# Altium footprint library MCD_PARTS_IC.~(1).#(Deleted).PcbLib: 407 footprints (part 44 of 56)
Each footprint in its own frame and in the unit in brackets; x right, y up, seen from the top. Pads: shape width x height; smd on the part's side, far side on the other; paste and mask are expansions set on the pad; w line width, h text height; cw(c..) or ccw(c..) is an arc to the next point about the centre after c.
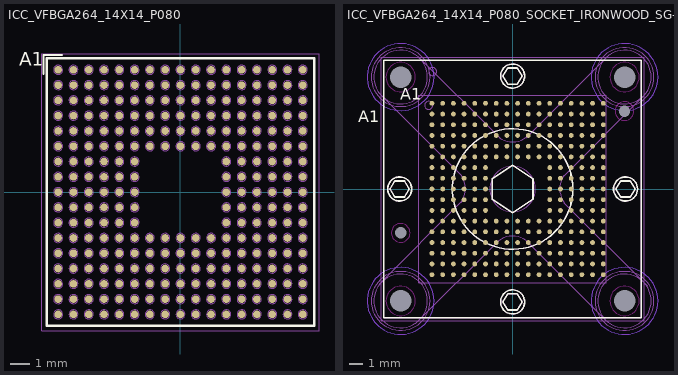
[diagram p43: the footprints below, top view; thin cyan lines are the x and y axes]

## ICC_VFBGA264_14X14_P080 [mm] "MCD-03176"
height 1
pads (264):
  round 0.4 smd mask+0.05: A1(-6.4,6.4) A2(-5.6,6.4) A3(-4.8,6.4) A4(-4,6.4) A5(-3.2,6.4) A6(-2.4,6.4) A7(-1.6,6.4) A8(-0.8,6.4) A9(0,6.4) A10(0.8,6.4) A11(1.6,6.4) A12(2.4,6.4) A13(3.2,6.4) A14(4,6.4) A15(4.8,6.4) A16(5.6,6.4) A17(6.4,6.4) B1(-6.4,5.6) B2(-5.6,5.6) B3(-4.8,5.6) B4(-4,5.6) B5(-3.2,5.6) B6(-2.4,5.6) B7(-1.6,5.6) B8(-0.8,5.6) B9(0,5.6) B10(0.8,5.6) B11(1.6,5.6) B12(2.4,5.6) B13(3.2,5.6) B14(4,5.6) B15(4.8,5.6) B16(5.6,5.6) B17(6.4,5.6) C1(-6.4,4.8) C2(-5.6,4.8) C3(-4.8,4.8) C4(-4,4.8) C5(-3.2,4.8) C6(-2.4,4.8) C7(-1.6,4.8) C8(-0.8,4.8) C9(0,4.8) C10(0.8,4.8) C11(1.6,4.8) C12(2.4,4.8) C13(3.2,4.8) C14(4,4.8) C15(4.8,4.8) C16(5.6,4.8) C17(6.4,4.8) D1(-6.4,4) D2(-5.6,4) D3(-4.8,4) D4(-4,4) D5(-3.2,4) D6(-2.4,4) D7(-1.6,4) D8(-0.8,4) D9(0,4) D10(0.8,4) D11(1.6,4) D12(2.4,4) D13(3.2,4) D14(4,4) D15(4.8,4) D16(5.6,4) D17(6.4,4) E1(-6.4,3.2) E2(-5.6,3.2) E3(-4.8,3.2) E4(-4,3.2) E5(-3.2,3.2) E6(-2.4,3.2) E7(-1.6,3.2) E8(-0.8,3.2) E9(0,3.2) E10(0.8,3.2) E11(1.6,3.2) E12(2.4,3.2) E13(3.2,3.2) E14(4,3.2) E15(4.8,3.2) E16(5.6,3.2) E17(6.4,3.2) F1(-6.4,2.4) F2(-5.6,2.4) F3(-4.8,2.4) F4(-4,2.4) F5(-3.2,2.4) F6(-2.4,2.4) F7(-1.6,2.4) F8(-0.8,2.4) F9(0,2.4) F10(0.8,2.4) F11(1.6,2.4) F12(2.4,2.4) F13(3.2,2.4) F14(4,2.4) F15(4.8,2.4) F16(5.6,2.4) F17(6.4,2.4) G1(-6.4,1.6) G2(-5.6,1.6) G3(-4.8,1.6) G4(-4,1.6) G5(-3.2,1.6) G6(-2.4,1.6) G12(2.4,1.6) G13(3.2,1.6) G14(4,1.6) G15(4.8,1.6) G16(5.6,1.6) G17(6.4,1.6) H1(-6.4,0.8) H2(-5.6,0.8) H3(-4.8,0.8) H4(-4,0.8) H5(-3.2,0.8) H6(-2.4,0.8) H12(2.4,0.8) H13(3.2,0.8) H14(4,0.8) H15(4.8,0.8) H16(5.6,0.8) H17(6.4,0.8) J1(-6.4,0) J2(-5.6,0) J3(-4.8,0) J4(-4,0) J5(-3.2,0) J6(-2.4,0) J12(2.4,0) J13(3.2,0) J14(4,0) J15(4.8,0) J16(5.6,0) J17(6.4,0) K1(-6.4,-0.8) K2(-5.6,-0.8) K3(-4.8,-0.8) K4(-4,-0.8) K5(-3.2,-0.8) K6(-2.4,-0.8) K12(2.4,-0.8) K13(3.2,-0.8) K14(4,-0.8) K15(4.8,-0.8) K16(5.6,-0.8) K17(6.4,-0.8) L1(-6.4,-1.6) L2(-5.6,-1.6) L3(-4.8,-1.6) L4(-4,-1.6) L5(-3.2,-1.6) L6(-2.4,-1.6) L12(2.4,-1.6) L13(3.2,-1.6) L14(4,-1.6) L15(4.8,-1.6) L16(5.6,-1.6) L17(6.4,-1.6) M1(-6.4,-2.4) M2(-5.6,-2.4) M3(-4.8,-2.4) M4(-4,-2.4) M5(-3.2,-2.4) M6(-2.4,-2.4) M7(-1.6,-2.4) M8(-0.8,-2.4) M9(0,-2.4) M10(0.8,-2.4) M11(1.6,-2.4) M12(2.4,-2.4) M13(3.2,-2.4) M14(4,-2.4) M15(4.8,-2.4) M16(5.6,-2.4) M17(6.4,-2.4) N1(-6.4,-3.2) N2(-5.6,-3.2) N3(-4.8,-3.2) N4(-4,-3.2) N5(-3.2,-3.2) N6(-2.4,-3.2) N7(-1.6,-3.2) N8(-0.8,-3.2) N9(0,-3.2) N10(0.8,-3.2) N11(1.6,-3.2) N12(2.4,-3.2) N13(3.2,-3.2) N14(4,-3.2) N15(4.8,-3.2) N16(5.6,-3.2) N17(6.4,-3.2) P1(-6.4,-4) P2(-5.6,-4) P3(-4.8,-4) P4(-4,-4) P5(-3.2,-4) P6(-2.4,-4) P7(-1.6,-4) P8(-0.8,-4) P9(0,-4) P10(0.8,-4) P11(1.6,-4) P12(2.4,-4) P13(3.2,-4) P14(4,-4) P15(4.8,-4) P16(5.6,-4) P17(6.4,-4) R1(-6.4,-4.8) R2(-5.6,-4.8) R3(-4.8,-4.8) R4(-4,-4.8) R5(-3.2,-4.8) R6(-2.4,-4.8) R7(-1.6,-4.8) R8(-0.8,-4.8) R9(0,-4.8) R10(0.8,-4.8) R11(1.6,-4.8) R12(2.4,-4.8) R13(3.2,-4.8) R14(4,-4.8) R15(4.8,-4.8) R16(5.6,-4.8) R17(6.4,-4.8) T1(-6.4,-5.6) T2(-5.6,-5.6) T3(-4.8,-5.6) T4(-4,-5.6) T5(-3.2,-5.6) T6(-2.4,-5.6) T7(-1.6,-5.6) T8(-0.8,-5.6) T9(0,-5.6) T10(0.8,-5.6) T11(1.6,-5.6) T12(2.4,-5.6) T13(3.2,-5.6) T14(4,-5.6) T15(4.8,-5.6) T16(5.6,-5.6) T17(6.4,-5.6) U1(-6.4,-6.4) U2(-5.6,-6.4) U3(-4.8,-6.4) U4(-4,-6.4) U5(-3.2,-6.4) U6(-2.4,-6.4) U7(-1.6,-6.4) U8(-0.8,-6.4) U9(0,-6.4) U10(0.8,-6.4) U11(1.6,-6.4) U12(2.4,-6.4) U13(3.2,-6.4) U14(4,-6.4) U15(4.8,-6.4) U16(5.6,-6.4) U17(6.4,-6.4)
Top Overlay:
  lines w0.12: -7.17,6.195 -7.17,7.17 -6.195,7.17 ; -7,-7 7,-7 7,7 -7,7 -7,-7
  text "A1" at -8.45,6.375 h1.2
M14-Top Assembly:
  drawing of 268 lines, arcs and shapes, not listed
  text "'.Designator'" at -2,-0.5 h0.75
  text "A1" at -6.8,6.175 h0.75
M16-Top Courtyard:
  lines w0.01: -7.25,-7.25 7.25,-7.25 7.25,7.25 -7.25,7.25 -7.25,-7.25
3D body: height 0.97, standoff 0.96, extent -6.249,5.776 -5.751,6.275
3D body: height 0.47, standoff -0.01, extent 2.96,-6.636 3.44,-6.164
3D body: height 0.47, standoff -0.01, extent 3.76,-6.636 4.24,-6.164
3D body: height 0.47, standoff -0.01, extent 4.56,-6.636 5.04,-6.164
3D body: height 0.47, standoff -0.01, extent 5.36,-6.636 5.84,-6.164
3D body: height 0.47, standoff -0.01, extent 6.16,-6.636 6.64,-6.164
3D body: height 0.47, standoff -0.01, extent -1.84,-6.636 -1.36,-6.164
3D body: height 0.47, standoff -0.01, extent -1.04,-6.636 -0.56,-6.164
3D body: height 0.47, standoff -0.01, extent -0.24,-6.636 0.24,-6.164
3D body: height 0.47, standoff -0.01, extent 0.56,-6.636 1.04,-6.164
3D body: height 0.47, standoff -0.01, extent 1.36,-6.636 1.84,-6.164
3D body: height 0.47, standoff -0.01, extent 2.16,-6.636 2.64,-6.164
3D body: height 0.47, standoff -0.01, extent -2.64,-6.636 -2.16,-6.164
3D body: height 0.47, standoff -0.01, extent -3.44,-6.636 -2.96,-6.164
3D body: height 0.47, standoff -0.01, extent -4.24,-6.636 -3.76,-6.164
3D body: height 0.47, standoff -0.01, extent -5.04,-6.636 -4.56,-6.164
3D body: height 0.47, standoff -0.01, extent -5.84,-6.636 -5.36,-6.164
3D body: height 0.47, standoff -0.01, extent -6.64,-6.636 -6.16,-6.164
3D body: height 0.47, standoff -0.01, extent 2.96,-5.836 3.44,-5.364
3D body: height 0.47, standoff -0.01, extent 3.76,-5.836 4.24,-5.364
3D body: height 0.47, standoff -0.01, extent 4.56,-5.836 5.04,-5.364
3D body: height 0.47, standoff -0.01, extent 5.36,-5.836 5.84,-5.364
3D body: height 0.47, standoff -0.01, extent 6.16,-5.836 6.64,-5.364
3D body: height 0.47, standoff -0.01, extent -1.84,-5.836 -1.36,-5.364
3D body: height 0.47, standoff -0.01, extent -1.04,-5.836 -0.56,-5.364
3D body: height 0.47, standoff -0.01, extent -0.24,-5.836 0.24,-5.364
3D body: height 0.47, standoff -0.01, extent 0.56,-5.836 1.04,-5.364
3D body: height 0.47, standoff -0.01, extent 1.36,-5.836 1.84,-5.364
3D body: height 0.47, standoff -0.01, extent 2.16,-5.836 2.64,-5.364
3D body: height 0.47, standoff -0.01, extent -2.64,-5.836 -2.16,-5.364
3D body: height 0.47, standoff -0.01, extent -3.44,-5.836 -2.96,-5.364
3D body: height 0.47, standoff -0.01, extent -4.24,-5.836 -3.76,-5.364
3D body: height 0.47, standoff -0.01, extent -5.04,-5.836 -4.56,-5.364
3D body: height 0.47, standoff -0.01, extent -5.84,-5.836 -5.36,-5.364
3D body: height 0.47, standoff -0.01, extent -6.64,-5.836 -6.16,-5.364
3D body: height 0.47, standoff -0.01, extent 2.96,-5.036 3.44,-4.564
3D body: height 0.47, standoff -0.01, extent 3.76,-5.036 4.24,-4.564
3D body: height 0.47, standoff -0.01, extent 4.56,-5.036 5.04,-4.564
3D body: height 0.47, standoff -0.01, extent 5.36,-5.036 5.84,-4.564
3D body: height 0.47, standoff -0.01, extent 6.16,-5.036 6.64,-4.564
3D body: height 0.47, standoff -0.01, extent -1.84,-5.036 -1.36,-4.564
3D body: height 0.47, standoff -0.01, extent -1.04,-5.036 -0.56,-4.564
3D body: height 0.47, standoff -0.01, extent -0.24,-5.036 0.24,-4.564
3D body: height 0.47, standoff -0.01, extent 0.56,-5.036 1.04,-4.564
3D body: height 0.47, standoff -0.01, extent 1.36,-5.036 1.84,-4.564
3D body: height 0.47, standoff -0.01, extent 2.16,-5.036 2.64,-4.564
3D body: height 0.47, standoff -0.01, extent -2.64,-5.036 -2.16,-4.564
3D body: height 0.47, standoff -0.01, extent -3.44,-5.036 -2.96,-4.564
3D body: height 0.47, standoff -0.01, extent -4.24,-5.036 -3.76,-4.564
3D body: height 0.47, standoff -0.01, extent -5.04,-5.036 -4.56,-4.564
3D body: height 0.47, standoff -0.01, extent -5.84,-5.036 -5.36,-4.564
3D body: height 0.47, standoff -0.01, extent -6.64,-5.036 -6.16,-4.564
3D body: height 0.47, standoff -0.01, extent 2.96,-4.236 3.44,-3.764
3D body: height 0.47, standoff -0.01, extent 3.76,-4.236 4.24,-3.764
3D body: height 0.47, standoff -0.01, extent 4.56,-4.236 5.04,-3.764
3D body: height 0.47, standoff -0.01, extent 5.36,-4.236 5.84,-3.764
3D body: height 0.47, standoff -0.01, extent 6.16,-4.236 6.64,-3.764
3D body: height 0.47, standoff -0.01, extent -1.84,-4.236 -1.36,-3.764
3D body: height 0.47, standoff -0.01, extent -1.04,-4.236 -0.56,-3.764
3D body: height 0.47, standoff -0.01, extent -0.24,-4.236 0.24,-3.764
3D body: height 0.47, standoff -0.01, extent 0.56,-4.236 1.04,-3.764
3D body: height 0.47, standoff -0.01, extent 1.36,-4.236 1.84,-3.764
3D body: height 0.47, standoff -0.01, extent 2.16,-4.236 2.64,-3.764
3D body: height 0.47, standoff -0.01, extent -2.64,-4.236 -2.16,-3.764
3D body: height 0.47, standoff -0.01, extent -3.44,-4.236 -2.96,-3.764
3D body: height 0.47, standoff -0.01, extent -4.24,-4.236 -3.76,-3.764
3D body: height 0.47, standoff -0.01, extent -5.04,-4.236 -4.56,-3.764
3D body: height 0.47, standoff -0.01, extent -5.84,-4.236 -5.36,-3.764
3D body: height 0.47, standoff -0.01, extent -6.64,-4.236 -6.16,-3.764
3D body: height 0.47, standoff -0.01, extent 2.96,-3.436 3.44,-2.964
3D body: height 0.47, standoff -0.01, extent 3.76,-3.436 4.24,-2.964
3D body: height 0.47, standoff -0.01, extent 4.56,-3.436 5.04,-2.964
3D body: height 0.47, standoff -0.01, extent 5.36,-3.436 5.84,-2.964
3D body: height 0.47, standoff -0.01, extent 6.16,-3.436 6.64,-2.964
3D body: height 0.47, standoff -0.01, extent -1.84,-3.436 -1.36,-2.964
3D body: height 0.47, standoff -0.01, extent -1.04,-3.436 -0.56,-2.964
3D body: height 0.47, standoff -0.01, extent -0.24,-3.436 0.24,-2.964
3D body: height 0.47, standoff -0.01, extent 0.56,-3.436 1.04,-2.964
3D body: height 0.47, standoff -0.01, extent 1.36,-3.436 1.84,-2.964
3D body: height 0.47, standoff -0.01, extent 2.16,-3.436 2.64,-2.964
3D body: height 0.47, standoff -0.01, extent -2.64,-3.436 -2.16,-2.964
3D body: height 0.47, standoff -0.01, extent -3.44,-3.436 -2.96,-2.964
3D body: height 0.47, standoff -0.01, extent -4.24,-3.436 -3.76,-2.964
3D body: height 0.47, standoff -0.01, extent -5.04,-3.436 -4.56,-2.964
3D body: height 0.47, standoff -0.01, extent -5.84,-3.436 -5.36,-2.964
3D body: height 0.47, standoff -0.01, extent -6.64,-3.436 -6.16,-2.964
3D body: height 0.47, standoff -0.01, extent 2.96,-2.636 3.44,-2.164
3D body: height 0.47, standoff -0.01, extent 3.76,-2.636 4.24,-2.164
3D body: height 0.47, standoff -0.01, extent 4.56,-2.636 5.04,-2.164
3D body: height 0.47, standoff -0.01, extent 5.36,-2.636 5.84,-2.164
3D body: height 0.47, standoff -0.01, extent 6.16,-2.636 6.64,-2.164
3D body: height 0.47, standoff -0.01, extent -1.84,-2.636 -1.36,-2.164
3D body: height 0.47, standoff -0.01, extent -1.04,-2.636 -0.56,-2.164
3D body: height 0.47, standoff -0.01, extent -0.24,-2.636 0.24,-2.164
3D body: height 0.47, standoff -0.01, extent 0.56,-2.636 1.04,-2.164
3D body: height 0.47, standoff -0.01, extent 1.36,-2.636 1.84,-2.164
3D body: height 0.47, standoff -0.01, extent 2.16,-2.636 2.64,-2.164
3D body: height 0.47, standoff -0.01, extent -2.64,-2.636 -2.16,-2.164
3D body: height 0.47, standoff -0.01, extent -3.44,-2.636 -2.96,-2.164
3D body: height 0.47, standoff -0.01, extent -4.24,-2.636 -3.76,-2.164
3D body: height 0.47, standoff -0.01, extent -5.04,-2.636 -4.56,-2.164
3D body: height 0.47, standoff -0.01, extent -5.84,-2.636 -5.36,-2.164
3D body: height 0.47, standoff -0.01, extent -6.64,-2.636 -6.16,-2.164
3D body: height 0.47, standoff -0.01, extent 2.96,2.164 3.44,2.636
3D body: height 0.47, standoff -0.01, extent 3.76,2.164 4.24,2.636
3D body: height 0.47, standoff -0.01, extent 4.56,2.164 5.04,2.636
3D body: height 0.47, standoff -0.01, extent 5.36,2.164 5.84,2.636
3D body: height 0.47, standoff -0.01, extent 6.16,2.164 6.64,2.636
3D body: height 0.47, standoff -0.01, extent -1.84,2.164 -1.36,2.636
3D body: height 0.47, standoff -0.01, extent -1.04,2.164 -0.56,2.636
3D body: height 0.47, standoff -0.01, extent -0.24,2.164 0.24,2.636
3D body: height 0.47, standoff -0.01, extent 0.56,2.164 1.04,2.636
3D body: height 0.47, standoff -0.01, extent 1.36,2.164 1.84,2.636
3D body: height 0.47, standoff -0.01, extent 2.16,2.164 2.64,2.636
3D body: height 0.47, standoff -0.01, extent -2.64,2.164 -2.16,2.636
3D body: height 0.47, standoff -0.01, extent -3.44,2.164 -2.96,2.636
3D body: height 0.47, standoff -0.01, extent -4.24,2.164 -3.76,2.636
3D body: height 0.47, standoff -0.01, extent -5.04,2.164 -4.56,2.636
3D body: height 0.47, standoff -0.01, extent -5.84,2.164 -5.36,2.636
3D body: height 0.47, standoff -0.01, extent -6.64,2.164 -6.16,2.636
3D body: height 0.47, standoff -0.01, extent 2.96,2.964 3.44,3.436
3D body: height 0.47, standoff -0.01, extent 3.76,2.964 4.24,3.436
3D body: height 0.47, standoff -0.01, extent 4.56,2.964 5.04,3.436
3D body: height 0.47, standoff -0.01, extent 5.36,2.964 5.84,3.436
3D body: height 0.47, standoff -0.01, extent 6.16,2.964 6.64,3.436
3D body: height 0.47, standoff -0.01, extent -1.84,2.964 -1.36,3.436
3D body: height 0.47, standoff -0.01, extent -1.04,2.964 -0.56,3.436
3D body: height 0.47, standoff -0.01, extent -0.24,2.964 0.24,3.436
3D body: height 0.47, standoff -0.01, extent 0.56,2.964 1.04,3.436
3D body: height 0.47, standoff -0.01, extent 1.36,2.964 1.84,3.436
3D body: height 0.47, standoff -0.01, extent 2.16,2.964 2.64,3.436
3D body: height 0.47, standoff -0.01, extent -2.64,2.964 -2.16,3.436
3D body: height 0.47, standoff -0.01, extent -3.44,2.964 -2.96,3.436
3D body: height 0.47, standoff -0.01, extent -4.24,2.964 -3.76,3.436
3D body: height 0.47, standoff -0.01, extent -5.04,2.964 -4.56,3.436
3D body: height 0.47, standoff -0.01, extent -5.84,2.964 -5.36,3.436
3D body: height 0.47, standoff -0.01, extent -6.64,2.964 -6.16,3.436
3D body: height 0.47, standoff -0.01, extent 2.96,3.764 3.44,4.236
3D body: height 0.47, standoff -0.01, extent 3.76,3.764 4.24,4.236
3D body: height 0.47, standoff -0.01, extent 4.56,3.764 5.04,4.236
3D body: height 0.47, standoff -0.01, extent 5.36,3.764 5.84,4.236
3D body: height 0.47, standoff -0.01, extent 6.16,3.764 6.64,4.236
3D body: height 0.47, standoff -0.01, extent -1.84,3.764 -1.36,4.236
3D body: height 0.47, standoff -0.01, extent -1.04,3.764 -0.56,4.236
3D body: height 0.47, standoff -0.01, extent -0.24,3.764 0.24,4.236
3D body: height 0.47, standoff -0.01, extent 0.56,3.764 1.04,4.236
3D body: height 0.47, standoff -0.01, extent 1.36,3.764 1.84,4.236
3D body: height 0.47, standoff -0.01, extent 2.16,3.764 2.64,4.236
3D body: height 0.47, standoff -0.01, extent -2.64,3.764 -2.16,4.236
3D body: height 0.47, standoff -0.01, extent -3.44,3.764 -2.96,4.236
3D body: height 0.47, standoff -0.01, extent -4.24,3.764 -3.76,4.236
3D body: height 0.47, standoff -0.01, extent -5.04,3.764 -4.56,4.236
3D body: height 0.47, standoff -0.01, extent -5.84,3.764 -5.36,4.236
3D body: height 0.47, standoff -0.01, extent -6.64,3.764 -6.16,4.236
3D body: height 0.47, standoff -0.01, extent 2.96,4.564 3.44,5.036
3D body: height 0.47, standoff -0.01, extent 3.76,4.564 4.24,5.036
3D body: height 0.47, standoff -0.01, extent 4.56,4.564 5.04,5.036
3D body: height 0.47, standoff -0.01, extent 5.36,4.564 5.84,5.036
3D body: height 0.47, standoff -0.01, extent 6.16,4.564 6.64,5.036
3D body: height 0.47, standoff -0.01, extent -1.84,4.564 -1.36,5.036
3D body: height 0.47, standoff -0.01, extent -1.04,4.564 -0.56,5.036
3D body: height 0.47, standoff -0.01, extent -0.24,4.564 0.24,5.036
3D body: height 0.47, standoff -0.01, extent 0.56,4.564 1.04,5.036
3D body: height 0.47, standoff -0.01, extent 1.36,4.564 1.84,5.036
3D body: height 0.47, standoff -0.01, extent 2.16,4.564 2.64,5.036
3D body: height 0.47, standoff -0.01, extent -2.64,4.564 -2.16,5.036
3D body: height 0.47, standoff -0.01, extent -3.44,4.564 -2.96,5.036
3D body: height 0.47, standoff -0.01, extent -4.24,4.564 -3.76,5.036
3D body: height 0.47, standoff -0.01, extent -5.04,4.564 -4.56,5.036
3D body: height 0.47, standoff -0.01, extent -5.84,4.564 -5.36,5.036
3D body: height 0.47, standoff -0.01, extent -6.64,4.564 -6.16,5.036
3D body: height 0.47, standoff -0.01, extent 2.96,5.364 3.44,5.836
3D body: height 0.47, standoff -0.01, extent 3.76,5.364 4.24,5.836
3D body: height 0.47, standoff -0.01, extent 4.56,5.364 5.04,5.836
3D body: height 0.47, standoff -0.01, extent 5.36,5.364 5.84,5.836
3D body: height 0.47, standoff -0.01, extent 6.16,5.364 6.64,5.836
3D body: height 0.47, standoff -0.01, extent -1.84,5.364 -1.36,5.836
3D body: height 0.47, standoff -0.01, extent -1.04,5.364 -0.56,5.836
3D body: height 0.47, standoff -0.01, extent -0.24,5.364 0.24,5.836
3D body: height 0.47, standoff -0.01, extent 0.56,5.364 1.04,5.836
3D body: height 0.47, standoff -0.01, extent 1.36,5.364 1.84,5.836
3D body: height 0.47, standoff -0.01, extent 2.16,5.364 2.64,5.836
3D body: height 0.47, standoff -0.01, extent -2.64,5.364 -2.16,5.836
3D body: height 0.47, standoff -0.01, extent -3.44,5.364 -2.96,5.836
3D body: height 0.47, standoff -0.01, extent -4.24,5.364 -3.76,5.836
3D body: height 0.47, standoff -0.01, extent -5.04,5.364 -4.56,5.836
3D body: height 0.47, standoff -0.01, extent -5.84,5.364 -5.36,5.836
3D body: height 0.47, standoff -0.01, extent -6.64,5.364 -6.16,5.836
3D body: height 0.47, standoff -0.01, extent 2.96,6.164 3.44,6.636
3D body: height 0.47, standoff -0.01, extent 3.76,6.164 4.24,6.636
3D body: height 0.47, standoff -0.01, extent 4.56,6.164 5.04,6.636
3D body: height 0.47, standoff -0.01, extent 5.36,6.164 5.84,6.636
3D body: height 0.47, standoff -0.01, extent 6.16,6.164 6.64,6.636
3D body: height 0.47, standoff -0.01, extent -1.84,6.164 -1.36,6.636
3D body: height 0.47, standoff -0.01, extent -1.04,6.164 -0.56,6.636
3D body: height 0.47, standoff -0.01, extent -0.24,6.164 0.24,6.636
3D body: height 0.47, standoff -0.01, extent 0.56,6.164 1.04,6.636
3D body: height 0.47, standoff -0.01, extent 1.36,6.164 1.84,6.636
3D body: height 0.47, standoff -0.01, extent 2.16,6.164 2.64,6.636
3D body: height 0.47, standoff -0.01, extent 2.16,1.364 2.64,1.836
3D body: height 0.47, standoff -0.01, extent 2.96,1.364 3.44,1.836
3D body: height 0.47, standoff -0.01, extent 3.76,1.364 4.24,1.836
3D body: height 0.47, standoff -0.01, extent 4.56,1.364 5.04,1.836
3D body: height 0.47, standoff -0.01, extent 5.36,1.364 5.84,1.836
3D body: height 0.47, standoff -0.01, extent 6.16,1.364 6.64,1.836
3D body: height 0.47, standoff -0.01, extent 2.16,0.564 2.64,1.036
3D body: height 0.47, standoff -0.01, extent 2.96,0.564 3.44,1.036
3D body: height 0.47, standoff -0.01, extent 3.76,0.564 4.24,1.036
3D body: height 0.47, standoff -0.01, extent 4.56,0.564 5.04,1.036
3D body: height 0.47, standoff -0.01, extent 5.36,0.564 5.84,1.036
3D body: height 0.47, standoff -0.01, extent 6.16,0.564 6.64,1.036
3D body: height 0.47, standoff -0.01, extent 2.16,-0.236 2.64,0.236
3D body: height 0.47, standoff -0.01, extent 2.96,-0.236 3.44,0.236
3D body: height 0.47, standoff -0.01, extent 3.76,-0.236 4.24,0.236
3D body: height 0.47, standoff -0.01, extent 4.56,-0.236 5.04,0.236
3D body: height 0.47, standoff -0.01, extent 5.36,-0.236 5.84,0.236
3D body: height 0.47, standoff -0.01, extent 6.16,-0.236 6.64,0.236
3D body: height 0.47, standoff -0.01, extent 2.16,-1.036 2.64,-0.564
3D body: height 0.47, standoff -0.01, extent 2.96,-1.036 3.44,-0.564
3D body: height 0.47, standoff -0.01, extent 3.76,-1.036 4.24,-0.564
3D body: height 0.47, standoff -0.01, extent 4.56,-1.036 5.04,-0.564
3D body: height 0.47, standoff -0.01, extent 5.36,-1.036 5.84,-0.564
3D body: height 0.47, standoff -0.01, extent 6.16,-1.036 6.64,-0.564
3D body: height 0.47, standoff -0.01, extent 2.16,-1.836 2.64,-1.364
3D body: height 0.47, standoff -0.01, extent 2.96,-1.836 3.44,-1.364
3D body: height 0.47, standoff -0.01, extent 3.76,-1.836 4.24,-1.364
3D body: height 0.47, standoff -0.01, extent 4.56,-1.836 5.04,-1.364
3D body: height 0.47, standoff -0.01, extent 5.36,-1.836 5.84,-1.364
3D body: height 0.47, standoff -0.01, extent 6.16,-1.836 6.64,-1.364
3D body: height 0.47, standoff -0.01, extent -2.64,-1.836 -2.16,-1.364
3D body: height 0.47, standoff -0.01, extent -3.44,-1.836 -2.96,-1.364
3D body: height 0.47, standoff -0.01, extent -4.24,-1.836 -3.76,-1.364
3D body: height 0.47, standoff -0.01, extent -5.04,-1.836 -4.56,-1.364
3D body: height 0.47, standoff -0.01, extent -5.84,-1.836 -5.36,-1.364
3D body: height 0.47, standoff -0.01, extent -6.64,-1.836 -6.16,-1.364
3D body: height 0.47, standoff -0.01, extent -2.64,-1.036 -2.16,-0.564
3D body: height 0.47, standoff -0.01, extent -3.44,-1.036 -2.96,-0.564
3D body: height 0.47, standoff -0.01, extent -4.24,-1.036 -3.76,-0.564
3D body: height 0.47, standoff -0.01, extent -5.04,-1.036 -4.56,-0.564
3D body: height 0.47, standoff -0.01, extent -5.84,-1.036 -5.36,-0.564
3D body: height 0.47, standoff -0.01, extent -6.64,-1.036 -6.16,-0.564
3D body: height 0.47, standoff -0.01, extent -2.64,-0.236 -2.16,0.236
3D body: height 0.47, standoff -0.01, extent -3.44,-0.236 -2.96,0.236
3D body: height 0.47, standoff -0.01, extent -4.24,-0.236 -3.76,0.236
3D body: height 0.47, standoff -0.01, extent -5.04,-0.236 -4.56,0.236
3D body: height 0.47, standoff -0.01, extent -5.84,-0.236 -5.36,0.236
3D body: height 0.47, standoff -0.01, extent -6.64,-0.236 -6.16,0.236
3D body: height 0.47, standoff -0.01, extent -2.64,0.564 -2.16,1.036
3D body: height 0.47, standoff -0.01, extent -3.44,0.564 -2.96,1.036
3D body: height 0.47, standoff -0.01, extent -4.24,0.564 -3.76,1.036
3D body: height 0.47, standoff -0.01, extent -5.04,0.564 -4.56,1.036
3D body: height 0.47, standoff -0.01, extent -5.84,0.564 -5.36,1.036
3D body: height 0.47, standoff -0.01, extent -6.64,0.564 -6.16,1.036
3D body: height 0.47, standoff -0.01, extent -2.64,1.364 -2.16,1.836
3D body: height 0.47, standoff -0.01, extent -3.44,1.364 -2.96,1.836
3D body: height 0.47, standoff -0.01, extent -4.24,1.364 -3.76,1.836
3D body: height 0.47, standoff -0.01, extent -5.04,1.364 -4.56,1.836
3D body: height 0.47, standoff -0.01, extent -5.84,1.364 -5.36,1.836
3D body: height 0.47, standoff -0.01, extent -6.64,1.364 -6.16,1.836
3D body: height 0.47, standoff -0.01, extent -2.64,6.164 -2.16,6.636
3D body: height 0.47, standoff -0.01, extent -3.44,6.164 -2.96,6.636
3D body: height 0.47, standoff -0.01, extent -4.24,6.164 -3.76,6.636
3D body: height 0.47, standoff -0.01, extent -5.04,6.164 -4.56,6.636
3D body: height 0.47, standoff -0.01, extent -5.84,6.164 -5.36,6.636
3D body: height 0.47, standoff -0.01, extent -6.64,6.164 -6.16,6.636
3D body: height 0.96, standoff 0.34, extent -7,-7 7,7

## ICC_VFBGA264_14X14_P080_SOCKET_IRONWOOD_SG-BGA-6112MF [mm] "MCD-03176"
height 8.25
pads (270):
  round 0.36 smd mask+0.05: A1(-6.025,6.4) A2(-5.225,6.4) A3(-4.425,6.4) A4(-3.625,6.4) A5(-2.825,6.4) A6(-2.025,6.4) A7(-1.225,6.4) A8(-0.425,6.4) A9(0.375,6.4) A10(1.175,6.4) A11(1.975,6.4) A12(2.775,6.4) A13(3.575,6.4) A14(4.375,6.4) A15(5.175,6.4) A16(5.975,6.4) A17(6.775,6.4) B1(-6.025,5.6) B2(-5.225,5.6) B3(-4.425,5.6) B4(-3.625,5.6) B5(-2.825,5.6) B6(-2.025,5.6) B7(-1.225,5.6) B8(-0.425,5.6) B9(0.375,5.6) B10(1.175,5.6) B11(1.975,5.6) B12(2.775,5.6) B13(3.575,5.6) B14(4.375,5.6) B15(5.175,5.6) B16(5.975,5.6) B17(6.775,5.6) C1(-6.025,4.8) C2(-5.225,4.8) C3(-4.425,4.8) C4(-3.625,4.8) C5(-2.825,4.8) C6(-2.025,4.8) C7(-1.225,4.8) C8(-0.425,4.8) C9(0.375,4.8) C10(1.175,4.8) C11(1.975,4.8) C12(2.775,4.8) C13(3.575,4.8) C14(4.375,4.8) C15(5.175,4.8) C16(5.975,4.8) C17(6.775,4.8) D1(-6.025,4) D2(-5.225,4) D3(-4.425,4) D4(-3.625,4) D5(-2.825,4) D6(-2.025,4) D7(-1.225,4) D8(-0.425,4) D9(0.375,4) D10(1.175,4) D11(1.975,4) D12(2.775,4) D13(3.575,4) D14(4.375,4) D15(5.175,4) D16(5.975,4) D17(6.775,4) E1(-6.025,3.2) E2(-5.225,3.2) E3(-4.425,3.2) E4(-3.625,3.2) E5(-2.825,3.2) E6(-2.025,3.2) E7(-1.225,3.2) E8(-0.425,3.2) E9(0.375,3.2) E10(1.175,3.2) E11(1.975,3.2) E12(2.775,3.2) E13(3.575,3.2) E14(4.375,3.2) E15(5.175,3.2) E16(5.975,3.2) E17(6.775,3.2) F1(-6.025,2.4) F2(-5.225,2.4) F3(-4.425,2.4) F4(-3.625,2.4) F5(-2.825,2.4) F6(-2.025,2.4) F7(-1.225,2.4) F8(-0.425,2.4) F9(0.375,2.4) F10(1.175,2.4) F11(1.975,2.4) F12(2.775,2.4) F13(3.575,2.4) F14(4.375,2.4) F15(5.175,2.4) F16(5.975,2.4) F17(6.775,2.4) G1(-6.025,1.6) G2(-5.225,1.6) G3(-4.425,1.6) G4(-3.625,1.6) G5(-2.825,1.6) G6(-2.025,1.6) G12(2.775,1.6) G13(3.575,1.6) G14(4.375,1.6) G15(5.175,1.6) G16(5.975,1.6) G17(6.775,1.6) H1(-6.025,0.8) H2(-5.225,0.8) H3(-4.425,0.8) H4(-3.625,0.8) H5(-2.825,0.8) H6(-2.025,0.8) H12(2.775,0.8) H13(3.575,0.8) H14(4.375,0.8) H15(5.175,0.8) H16(5.975,0.8) H17(6.775,0.8) J1(-6.025,0) J2(-5.225,0) J3(-4.425,0) J4(-3.625,0) J5(-2.825,0) J6(-2.025,0) J12(2.775,0) J13(3.575,0) J14(4.375,0) J15(5.175,0) J16(5.975,0) J17(6.775,0) K1(-6.025,-0.8) K2(-5.225,-0.8) K3(-4.425,-0.8) K4(-3.625,-0.8) K5(-2.825,-0.8) K6(-2.025,-0.8) K12(2.775,-0.8) K13(3.575,-0.8) K14(4.375,-0.8) K15(5.175,-0.8) K16(5.975,-0.8) K17(6.775,-0.8) L1(-6.025,-1.6) L2(-5.225,-1.6) L3(-4.425,-1.6) L4(-3.625,-1.6) L5(-2.825,-1.6) L6(-2.025,-1.6) L12(2.775,-1.6) L13(3.575,-1.6) L14(4.375,-1.6) L15(5.175,-1.6) L16(5.975,-1.6) L17(6.775,-1.6) M1(-6.025,-2.4) M2(-5.225,-2.4) M3(-4.425,-2.4) M4(-3.625,-2.4) M5(-2.825,-2.4) M6(-2.025,-2.4) M7(-1.225,-2.4) M8(-0.425,-2.4) M9(0.375,-2.4) M10(1.175,-2.4) M11(1.975,-2.4) M12(2.775,-2.4) M13(3.575,-2.4) M14(4.375,-2.4) M15(5.175,-2.4) M16(5.975,-2.4) M17(6.775,-2.4) N1(-6.025,-3.2) N2(-5.225,-3.2) N3(-4.425,-3.2) N4(-3.625,-3.2) N5(-2.825,-3.2) N6(-2.025,-3.2) N7(-1.225,-3.2) N8(-0.425,-3.2) N9(0.375,-3.2) N10(1.175,-3.2) N11(1.975,-3.2) N12(2.775,-3.2) N13(3.575,-3.2) N14(4.375,-3.2) N15(5.175,-3.2) N16(5.975,-3.2) N17(6.775,-3.2) P1(-6.025,-4) P2(-5.225,-4) P3(-4.425,-4) P4(-3.625,-4) P5(-2.825,-4) P6(-2.025,-4) P7(-1.225,-4) P8(-0.425,-4) P9(0.375,-4) P10(1.175,-4) P11(1.975,-4) P12(2.775,-4) P13(3.575,-4) P14(4.375,-4) P15(5.175,-4) P16(5.975,-4) P17(6.775,-4) R1(-6.025,-4.8) R2(-5.225,-4.8) R3(-4.425,-4.8) R4(-3.625,-4.8) R5(-2.825,-4.8) R6(-2.025,-4.8) R7(-1.225,-4.8) R8(-0.425,-4.8) R9(0.375,-4.8) R10(1.175,-4.8) R11(1.975,-4.8) R12(2.775,-4.8) R13(3.575,-4.8) R14(4.375,-4.8) R15(5.175,-4.8) R16(5.975,-4.8) R17(6.775,-4.8) T1(-6.025,-5.6) T2(-5.225,-5.6) T3(-4.425,-5.6) T4(-3.625,-5.6) T5(-2.825,-5.6) T6(-2.025,-5.6) T7(-1.225,-5.6) T8(-0.425,-5.6) T9(0.375,-5.6) T10(1.175,-5.6) T11(1.975,-5.6) T12(2.775,-5.6) T13(3.575,-5.6) T14(4.375,-5.6) T15(5.175,-5.6) T16(5.975,-5.6) T17(6.775,-5.6) U1(-6.025,-6.4) U2(-5.225,-6.4) U3(-4.425,-6.4) U4(-3.625,-6.4) U5(-2.825,-6.4) U6(-2.025,-6.4) U7(-1.225,-6.4) U8(-0.425,-6.4) U9(0.375,-6.4) U10(1.175,-6.4) U11(1.975,-6.4) U12(2.775,-6.4) U13(3.575,-6.4) U14(4.375,-6.4) U15(5.175,-6.4) U16(5.975,-6.4) u17(6.775,-6.4)
  round 0 hole 1.61 unplated mask+0.05: NPTH1(-8.363,8.363) NPTH2(8.363,8.363) NPTH3(8.363,-8.363) NPTH4(-8.363,-8.363)
  round 0 hole 0.85 unplated mask+0.05: NPTH5(-8.363,-3.283) NPTH6(8.363,5.823)
Bottom Layer keep-out:
  circle w0.01: c-8.362,8.362 r2.5
  circle w0.01: c8.363,8.363 r2.5
  circle w0.01: c8.363,-8.363 r2.5
  circle w0.01: c-8.363,-8.363 r2.5
Top Overlay:
  circle w0.12: c0,0 r4.5
  circle w0.12: c-8.438,0 r0.9
  circle w0.12: c0,-8.438 r0.9
  circle w0.12: c8.438,0 r0.9
  circle w0.12: c0,8.437 r0.9
  lines w0.12: -9.613,-9.613 9.613,-9.613 9.613,9.613 -9.613,9.613 -9.613,-9.613 ; -9.158,0 -8.798,0.6 -8.078,0.6 -7.718,0 -8.078,-0.6 -8.798,-0.6 -9.158,0 ; -1.524,-0.762 0,-1.778 1.524,-0.762 1.524,0.762 0,1.778 -1.524,0.762 -1.524,-0.762 ; -0.72,-8.438 -0.36,-7.838 0.36,-7.838 0.72,-8.438 0.36,-9.038 -0.36,-9.038 -0.72,-8.438 ; -0.72,8.437 -0.36,7.837 0.36,7.837 0.72,8.437 0.36,9.037 -0.36,9.037 -0.72,8.437 ; 7.718,0 8.078,0.6 8.798,0.6 9.158,0 8.798,-0.6 8.078,-0.6 7.718,0
  text "A1" at -8.4,6.375 h1.5
  text "A1" at -11.55,4.675 h1.5
Bottom Overlay:
  circle w0.12: c-8.363,8.363 r2.5
  circle w0.12: c-8.362,-8.362 r2.5
  circle w0.12: c8.362,-8.362 r2.5
  circle w0.12: c8.363,8.363 r2.5
Keep-Out Layer:
  circle w0.01: c8.363,5.823 r0.7
  circle w0.01: c-8.363,-3.283 r0.7
  circle w0.01: c-8.362,8.362 r1.1
  circle w0.01: c8.363,8.363 r1.1
  circle w0.01: c8.362,-8.362 r1.1
  circle w0.01: c-8.363,-8.363 r1.1
M14-Top Assembly:
  circle w0.01: c0,0 r4.5
  circle w0.01: c-8.438,0 r0.9
  circle w0.01: c0,-8.438 r0.9
  circle w0.01: c8.438,0 r0.9
  circle w0.01: c0,8.437 r0.9
  circle w0.01: c-5.975,8.775 r0.3
  circle w0.01: c-6.275,6.25 r0.3
  lines w0.01: -9.613,-9.613 9.613,-9.613 9.613,3.562 9.613,9.613 -9.613,9.613 -9.613,-9.613 ; -9.158,0 -8.798,-0.6 -8.078,-0.6 -7.718,0 -8.078,0.6 -8.798,0.6 -9.158,0 ; -7,-7 7,-7 7,7 -7,7 -7,-7 ; -1.524,-0.762 0,-1.778 1.524,-0.762 1.524,0.762 0,1.778 -1.524,0.762 -1.524,-0.762 ; -0.72,-8.438 -0.36,-9.038 0.36,-9.038 0.72,-8.438 0.36,-7.838 -0.36,-7.838 -0.72,-8.438 ; -0.72,8.437 -0.36,9.037 0.36,9.037 0.72,8.437 0.36,7.837 -0.36,7.837 -0.72,8.437 ; 7.718,0 8.078,-0.6 8.798,-0.6 9.158,0 8.798,0.6 8.078,0.6 7.718,0
  text "'.Designator'" at 0,0 h0.75
M15-Bottom Assembly:
  circle w0.01: c-8.362,8.362 r2
  circle w0.01: c-8.362,-8.362 r2
  circle w0.01: c8.363,-8.363 r2
  circle w0.01: c8.362,8.362 r2
  lines w0.01: -10.044,7.235 -3.82,1.011 ; -9.929,-7.075 -3.82,-0.967 ; -7.235,-10.044 -1.011,-3.82 ; -7.075,9.929 -0.967,3.82 ; -3.848,1.029 cw(c-5.325,0) -3.826,-0.996 ; -1.029,-3.848 cw(c0,-5.325) 0.996,-3.826 ; -0.996,3.826 ccw(c0,5.325) 1.029,3.848 ; 0.967,-3.82 7.075,-9.929 ; 1.011,3.82 7.235,10.044 ; 3.82,-1.011 10.044,-7.235 ; 3.82,0.967 9.928,7.075 ; 3.826,0.996 ccw(c5.325,0) 3.848,-1.029
M16-Top Courtyard:
  lines w0.01: -9.825,-9.825 -9.825,9.825 9.825,9.825 9.825,-9.825 -9.825,-9.825
M17-Bottom Courtyard:
  circle w0.01: c0,0 r1.7
  circle w0.01: c-8.362,8.362 r2.2
  circle w0.01: c8.362,8.362 r2.2
  circle w0.01: c8.362,-8.362 r2.2
  circle w0.01: c-8.362,-8.362 r2.2
3D body: height 6, standoff 5, extent -9.33,-0.898 -7.537,0.898
3D body: height 6.01, standoff 6, extent -9.158,-0.6 -7.718,0.6
3D body: height 6, standoff 5, extent -0.893,7.539 0.9,9.336
3D body: height 6.01, standoff 6, extent -0.72,7.837 0.72,9.037
3D body: height 6, standoff 5, extent 7.545,-0.898 9.338,0.898
3D body: height 6.01, standoff 6, extent 7.717,-0.6 9.158,0.6
3D body: height 6, standoff 5, extent -0.893,-9.336 0.9,-7.539
3D body: height 6.01, standoff 6, extent -0.72,-9.038 0.72,-7.838
3D body: height 9.85, standoff 1.6, extent -2.5,-2.497 2.5,2.497
3D body: height 9.86, standoff 9.85, extent -1.025,-1.212 1.025,1.213
3D body: height 5, standoff 0, extent -9.613,-9.613 9.613,9.613
3D body: height -1.6, standoff -6.6, extent -10.375,8.362 -6.362,10.375
3D body: height -1.6, standoff -6.6, extent -10.375,6.362 -6.363,8.375
3D body: height -1.6, standoff -6.6, extent 6.35,6.362 10.362,8.375
3D body: height -1.6, standoff -6.6, extent 6.35,8.362 10.363,10.375
3D body: height -1.6, standoff -6.6, extent 6.35,-10.363 10.362,-8.35
3D body: height -1.6, standoff -6.6, extent 6.35,-8.363 10.363,-6.35
3D body: height -1.6, standoff -6.6, extent -10.375,-10.363 -6.363,-8.35
3D body: height -1.6, standoff -6.6, extent -10.375,-8.363 -6.362,-6.35
3D body: height -1.6, standoff -6.6, extent -1.5,-1.5 1.5,1.5
3D body: height -4.1, standoff -6.6, extent -10.044,-10.044 10.044,10.044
